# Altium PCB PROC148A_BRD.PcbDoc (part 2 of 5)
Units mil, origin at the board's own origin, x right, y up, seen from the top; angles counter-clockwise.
Board outline 7150 x 3764 mil, 4 copper layers (Top Layer, GND01, PWR/GND02, Bottom Layer), stack 60.96 mil thick; 312 components, 352 nets, 2206 pads, 423 vias.
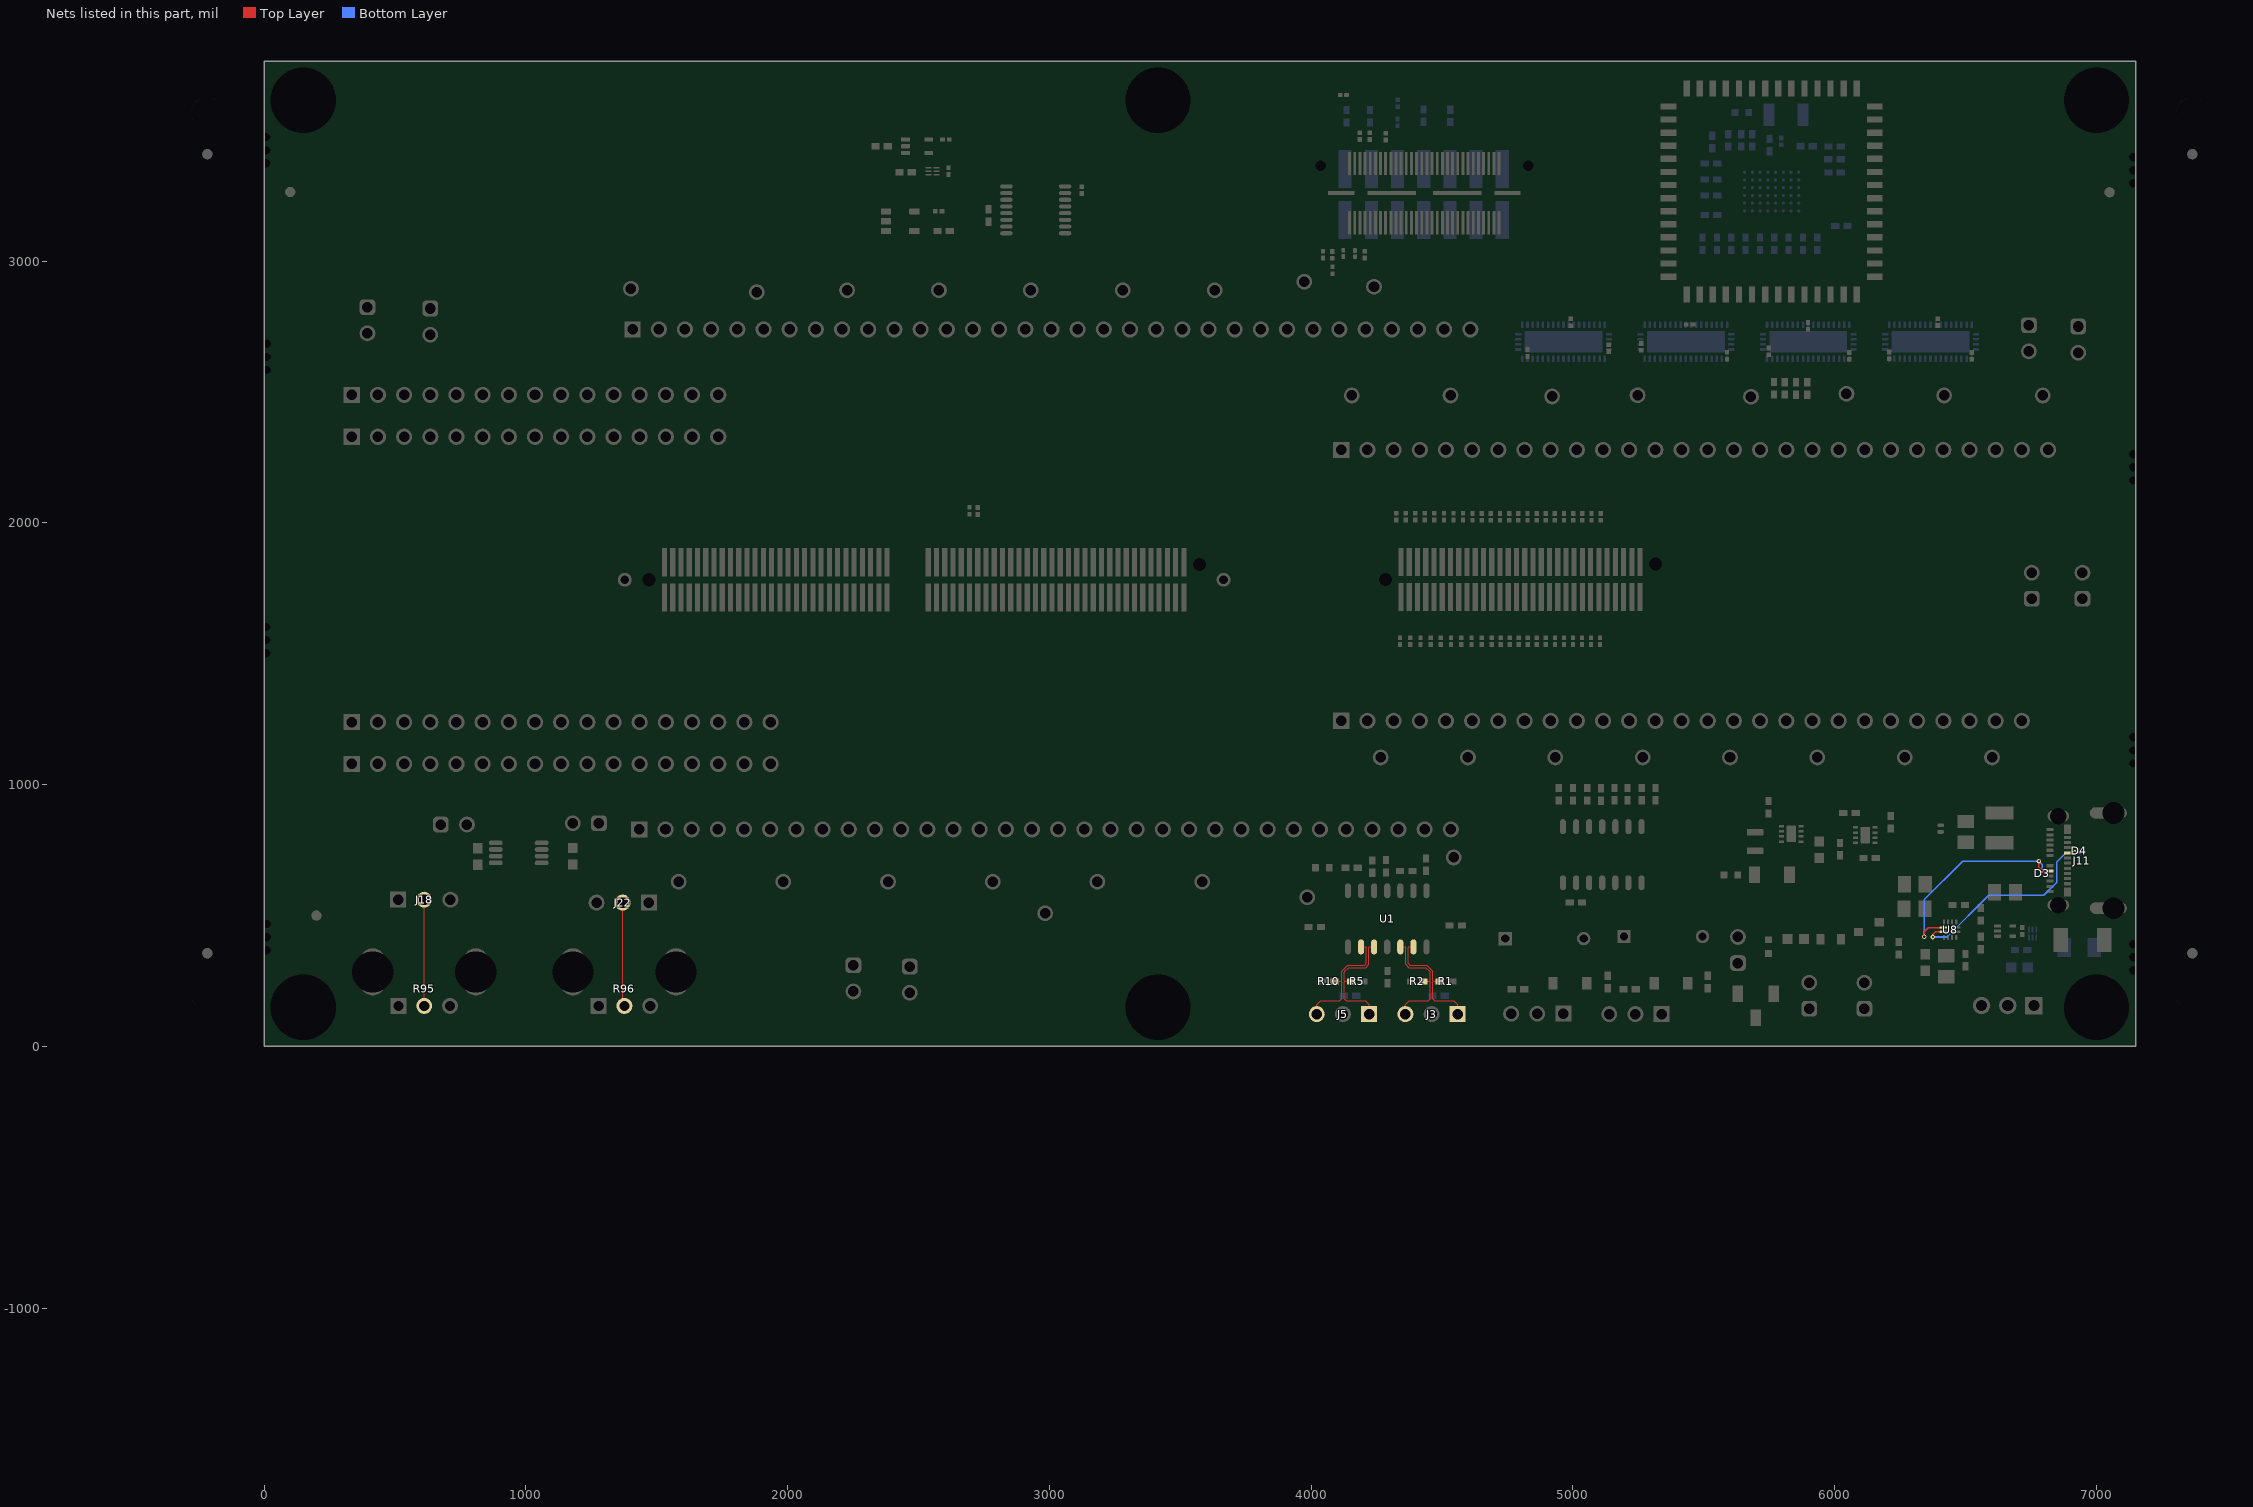
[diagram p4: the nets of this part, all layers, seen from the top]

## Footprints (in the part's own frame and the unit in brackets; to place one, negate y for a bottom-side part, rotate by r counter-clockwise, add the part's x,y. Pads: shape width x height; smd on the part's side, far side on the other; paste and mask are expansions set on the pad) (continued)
SOD-123 [mm] "On Semi recommended land pattern"
  rect 0.915x1.22 smd: 1(-1.637,0) 2(1.637,0)
  silkscreen extent -2.74,-1.17 2.03,1.17, body extent -1.93,-0.9 1.93,0.9, height 1.35
SW_CAS-120TA [mm] "COPAL ELECTRONICS"
  rect 1.6x1 smd: 1(-1.15,1.75) 2(1.15,0) 3(-1.15,-1.75)
  silkscreen extent -2,-2.85 1.4,2.92, body extent -1.4,-2.85 1.4,2.85, height 2.51
TFM201610ALMA [mm] "TDK"
  rrect17% 0.6x1.6 smd: 1(-0.9,0) 2(0.9,0)
  body extent -1.1,-0.9 1.1,0.9, height 1
TI_Stacked_Overlay_Small [mil]
  silkscreen extent -418,-98 418,98
WEEE_Minimum [mil] "WEEElie bin"
  silkscreen extent -95,-172 99,104
Wurth_60900213421 [mil] "Shunt, 2.54mm, Black"
  round 1 on Mech3: 0(0,0)
  body extent -98,-48 98,48, height 338

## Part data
C1 C2 C5: library part CMP-0006675-2, "CAP, CERM, 0.1 uF, 50 V, +/- 20%, X7R, 0402", Cap_Case=0402, Manufacturer=MuRata, Supplier Part Number 1=490-10701-1-ND, TempCo=X7R, Tolerance_%=20%, Value1=Unknown, Value2=50V, ValueDisplayed=0.1uF
C3 C4: library part CMP-0006712-2, "CAP, CERM, 4700 pF, 100 V, +/- 10%, X7R, 0402", Cap_Case=0402, Manufacturer=MuRata, Supplier Part Number 1=490-3885-1-ND, TempCo=X7R, Tolerance_%=10%, Value1=Unknown, Value2=100V, ValueDisplayed=4700pF
C6 C7: library part CMP-0084239-1, "CAP, CERM, 220 pF, 50 V,+/- 10%, X8R, AEC-Q200 Grade 0, 0402", Cap_Case=0402, Manufacturer=TDK, TempCo=X8R, Tolerance_%=10%, Value2=50V, ValueDisplayed=220pF
C8 C26 C27 C29: library part CMP-0007727-2, "CAP, CERM, 0.1 uF, 50 V, +/- 20%, X7R, 0805", Cap_Case=0805, Manufacturer=Kemet, Supplier Part Number 1=399-1169-1-ND, TempCo=X7R, Tolerance_%=20%, Value1="0.064 ohm", Value2=50V, ValueDisplayed=0.1uF
C9 C11 C12 C13 C14 C15 C16 C17 C18 C19 C20 C21 C22 C23 C24 C25 C37 C38 C39 C40 C43: library part CMP-0009717-2, "CAP, CERM, 0.1 uF, 16 V, +/- 10%, X5R, 0201", Cap_Case=0201, Manufacturer=MuRata, Supplier Part Number 1=490-9985-1-ND, TempCo=X5R, Tolerance_%=10%, Value1=Unknown, Value2=16V, ValueDisplayed=0.1uF
C10: library part CMP-0081135-1, "CAP, CERM, 10 µF, 50 V,+/- 10%, X7R, 1210", Cap_Case=1210, Manufacturer=MuRata, Supplier Part Number 1=490-10961-1-ND, TempCo=X7R, Tolerance_%=10%, Value1="0.001 ohm", Value2=50V, ValueDisplayed=10µF
C28: library part CMP-0079201-1, "CAP, CERM, 10 µF, 50 V,+/- 10%, X7R, 1210", Cap_Case=1210, Manufacturer="Samsung Electro-Mechanics", Supplier Part Number 1=1276-3388-1-ND, TempCo=X7R, Tolerance_%=10%, Value1="0.005 ohm", Value2=50V, ValueDisplayed=10µF
C30 C41: library part CMP-0007206-4, "CAP, CERM, 300 pF, 50 V, +/- 5%, C0G/NP0, 0603", Cap_Case=0603, Manufacturer=MuRata, Supplier Part Number 1=490-1438-1-ND, TempCo=C0G/NP0, Tolerance_%=5%, Value1=Unknown, Value2=50V, ValueDisplayed=300pF
C31: library part CMP-0006412-2, "CAP, CERM, 1000 pF, 50 V, +/- 5%, C0G/NP0, 0402", Cap_Case=0402, Manufacturer=MuRata, Supplier Part Number 1=490-3244-1-ND, TempCo=C0G/NP0, Tolerance_%=5%, Value1=Unknown, Value2=50V, ValueDisplayed=1000pF
C32: library part CMP-0008959-2, "CAP, CERM, 22 uF, 10 V, +/- 10%, X7R, 1206", Cap_Case=1206, Manufacturer=MuRata, Supplier Part Number 1=490-5309-1-ND, TempCo=X7R, Tolerance_%=10%, Value1=Unknown, Value2=10V, ValueDisplayed=22uF
C33: library part CMP-0007501-5, "CAP, CERM, 10 uF, 25 V, +/- 20%, X5R, 0603", Cap_Case=0603, Manufacturer=MuRata, Supplier Part Number 1=490-12323-1-ND, TempCo=X5R, Tolerance_%=20%, Value1=Unknown, Value2=25V, ValueDisplayed=10uF
C34: library part CMP-0009436-2, "CAP, CERM, 1000 pF, 2000 V, +/- 10%, X7R, 1808", Cap_Case=1808, Manufacturer=MuRata, Supplier Part Number 1=490-8145-1-ND, TempCo=X7R, Tolerance_%=10%, Value1=Unknown, Value2=2000V, ValueDisplayed=1000pF
C35 C36: library part CMP-0006608-2, "CAP, CERM, 1 uF, 25 V, +/- 10%, X5R, 0402", Cap_Case=0402, Manufacturer=MuRata, Supplier Part Number 1=490-10017-1-ND, TempCo=X5R, Tolerance_%=10%, Value1=Unknown, Value2=25V, ValueDisplayed=1uF
C44: library part CMP-0007174-4, "CAP, CERM, 0.01 uF, 50 V, +/- 5%, C0G/NP0, 0603", Cap_Case=0603, Manufacturer=MuRata, Supplier Part Number 1=490-9666-1-ND, TempCo=C0G/NP0, Tolerance_%=5%, Value1=Unknown, Value2=50V, ValueDisplayed=0.01uF
D1 D6: library part CMP-0029001-2, "Diode, Ultrafast, 100 V, 0.15 A, SOD-123", Manufacturer="Diodes Inc.", Value1=0.15A, Value2=1.25V
D2: library part CMP-0073591-4, "Automotive 1-Channel Ultra-Low-Capacitance IEC ESD Protection Diode, DPY0002A (X1SON-2)", Alternate Manufacturer="Texas Instruments", Alternate PartNumber=TPD1E05U06QDPYTQ1, Operating Temperature Range="-40 to 125 C", Rating=Automotive
D3 D4: library part CMP-0073601-1, "1-Channel ESD Protection Diode for USB Type-C and Thunderbolt 3, DPL0002A (X2SON-2)", Alternate Manufacturer="Texas Instruments", Alternate PartNumber=TPD1E01B04DPLT
D5: library part CMP-0002879-2, "LED, Green, SMD", Color=green, Manufacturer=OSRAM, Value1=W, Value2=1.8V
FB3 FB4 FB5 FB6: library part CMP-0089199-1, "120 Ohms @ 100MHz 1  Ferrite Bead 0603 (1608 Metric) 2A 40mOhm", Digikey Part Number=490-3991-1-ND, Impedance At Frequency="120O @ 100MHz", Manufacturer=Murata, Mouser Part Number=81-BLM18EG121SN1D, Operating Temperature Range="-55°C to +125°C", Tolerance_%=25%
FID1 FID2 FID3 FID4 FID5 FID6: library part CMP-0077181-1, "Fiducial mark.  There is nothing to buy or mount.", Manufacturer=N/A
J1: library part CMP-0003859-2, "C2000 controlCARD-180HSEC (60-pin addon) connector, SMT", Manufacturer=Samtec
J2: library part CMP-0003814-2, "C2000 controlCARD-120HSEC connector, SMT", Manufacturer=Samtec
J3 J5 J7 J8 J18 J22: library part CMP-0055332-1, "Header, 2.54mm, 3x1, Tin, TH", Color=Black, Current_A=4A, Manufacturer=Molex, Supplier Part Number 1=WM50016-03-ND, Voltage_V=250V
J4 J13 J16 J17 J19 J23 J26 J27 J28 J29 J30 J65 J66: library part CMP-0077643-1, "Header, 2.54mm, 2x1, Gold, TH", Color=Black, Current_A=5.7A, Manufacturer=Samtec, Supplier Part Number 1=SAM1038-02-ND, Voltage_V=550V
J6 J14: library part CMP-02766-001472-1, "CONN HEADER VERT 17POS 2.54MM", Color=Black, Package Quantity=1
J9: library part CMP-0075524-1, "Receptacle, 0.5 mm, 30x2, Gold, TH", Color=Black, Manufacturer=Samtec, PartNumber=QSH-030-01-L-D-A, Supplier Part Number 1=SAM8180-ND
J10: library part CMP-0075611-2, "Header, 2.54mm, 7x2, Gold, SMT", Color=Black, Current_A=5.4A, Manufacturer=Samtec, Supplier Part Number 1=TSM-107-01-L-DV-ND
J11: library part CMP-0093552-1, "USB-C (USB TYPE-C) USB 3.2 Gen 2 (USB 3.1 Gen 2, Superspeed + (USB 3.1)) Receptacle Connector 24 Position Surface Mount, Right Angle; Through Hole", Digikey Part Number=WM17992CT-ND, Manufacturer=Molex, Mouser Part Number=538-201267-0005, Operating Temperature Range="-40°C to +105°C", Voltage_V=30V
J12 J15: library part CMP-02766-001466-1, "CONN HEADER VERT 15POS 2.54MM", Color=Black
J20: library part CMP-02766-001470-1, "CONN HEADER VERT 32POS 2.54MM", Color=Black, Package Quantity=1
J21: library part CMP-02766-001386-1, "CONN HEADER VERT 33POS 2.54MM", Color=Black
J24: library part CMP-02766-001392-1, "CONN HEADER VERT 27POS 2.54MM", Color=Black, Package Quantity=1
J25: library part CMP-02766-001385-1, "CONN HEADER VERT 28POS 2.54MM", Color=Black, Package Quantity=1
J31 J32 J33 J34 J35 J36 J37 J38 J39 J40 J41 J42 J43 J44 J45 J46 J47 J48 J49 J50 J51 J52 J53 J54 J55 J56 J57 J58 J59 J60 J61 J62 J63 J64: library part CMP-0079328-1, "Header, 2.54mm, 1x1, Gold, TH", Color=Black, Manufacturer=Samtec, Supplier Part Number 1=SAM1038-01-ND
L1: library part CMP-0081094-1, "Inductor, Shielded, Metal Composite, 2.2 µH, 1.9 A, 0.152 ohm, AEC-Q200 Grade 0, SMD", Manufacturer=TDK, Supplier Part Number 1=445-174576-1-ND, Value1="0.152 ohm", Value2=1.9A, ValueDisplayed=2.2µH
Logo1: library part CMP-0074844-1
Logo2: library part CMP-0074838-1, "Texas Instrument Corporate Signature"
Logo3: library part CMP-0074847-1, "FCC_disclaimer"
Logo4: library part CMP-0074769-1
Q1: library part CMP-1058-00767-1, "Power MOSFET, 200 mA, 50 V, N-Channel, 3-Pin SOT-23, Pb-Free, Tape and Reel", Manufacturer="On Semiconductor", Package Type=SOT-23-3
R1 R2 R5 R10: library part CMP-0026462-2, "RES, 59.0, 1%, 0.063 W, AEC-Q200 Grade 0, 0402", Manufacturer=Vishay-Dale, Power_W=63mW, Supplier Part Number 1=541-59.0LCT-ND, TempCo="100 ppm/C", Tolerance_%=1%, Value2=0.063W, Value_Code=59R0, ValueDisplayed=59.0
R3 R6 R53 R56 R89 R92: library part CMP-0026822-3, "RES, 0, 5%, 0.063 W, AEC-Q200 Grade 0, 0402", Manufacturer=Vishay-Dale, Power_W=63mW, Supplier Part Number 1=541-0.0JCT-ND, TempCo="200 ppm/C", Tolerance_%=5%, Value2=0.063W, Value_Code=0000, ValueDisplayed=0
R4 R7 R88 R91: library part CMP-0026908-3, "RES, 33, 5%, 0.063 W, AEC-Q200 Grade 0, 0402", Manufacturer=Vishay-Dale, Power_W=63mW, Supplier Part Number 1=541-33JCT-ND, TempCo="200 ppm/C", Tolerance_%=5%, Value2=0.063W, Value_Code=33R0, ValueDisplayed=33
R8 R9: library part CMP-0026994-4, "RES, 10 k, 5%, 0.1 W, AEC-Q200 Grade 0, 0402", Manufacturer=Panasonic, Power_W=100mW, Supplier Part Number 1=P10KJCT-ND, TempCo="200 ppm/C", Tolerance_%=5%, Value2=0.1W, Value_Code=10k0, ValueDisplayed=10k
R11: library part CMP-0026829-3, "RES, 110, 5%, 0.063 W, AEC-Q200 Grade 0, 0402", Manufacturer=Vishay-Dale, Power_W=63mW, Supplier Part Number 1=541-110JCT-ND, TempCo="200 ppm/C", Tolerance_%=5%, Value2=0.063W, Value_Code=110R, ValueDisplayed=110
R12 R48 R59 R60 R61 R62 R63 R64 R65 R66 R67 R68 R69 R70 R71 R72: library part CMP-0026880-3, "RES, 22, 5%, 0.063 W, AEC-Q200 Grade 0, 0402", Manufacturer=Vishay-Dale, Power_W=63mW, Supplier Part Number 1=541-22JCT-ND, TempCo="200 ppm/C", Tolerance_%=5%, Value2=0.063W, Value_Code=22R0, ValueDisplayed=22
R13 R14 R20 R22 R37 R38 R39 R73 R74 R75 R76 R77 R78 R79 R80 R81 R82 R83 R85 R86 R87 R90 R93: library part CMP-0026825-5, "RES, 10 k, 5%, 0.063 W, AEC-Q200 Grade 0, 0402", Manufacturer=Vishay-Dale, Power_W=63mW, Supplier Part Number 1=541-10KJCT-ND, TempCo="200 ppm/C", Tolerance_%=5%, Value2=0.063W, Value_Code=10k0, ValueDisplayed=10k
R15 R16 R23: library part CMP-0083836-1, "RES, 100, 1%, 0.05 W, 0201", Manufacturer=Vishay-Semiconductor, Power_W=50mW, TempCo="100 ppm/C", Tolerance_%=1%, Value2=0.05W, Value_Code=100R, ValueDisplayed=100
R17: library part CMP-0027280-3, "RES, 4.70 k, 1%, 0.05 W, 0201", Manufacturer=Vishay-Dale, Power_W=50mW, Supplier Part Number 1=541-4.70KAABCT-ND, TempCo="100 ppm/C", Tolerance_%=1%, Value2=0.05W, Value_Code=4k70, ValueDisplayed=4.70k
R18 R19 R21: library part CMP-0089575-2, "Res Thick Film 0201 33.2 Ohm 1% 0.05W(1/20W) ±200ppm/C Pad SMD Automotive T/R", Digikey Part Number=P122945CT-ND, Manufacturer=Panasonic, Mouser Part Number=667-ERJ-1GNF33R2C, Operating Temperature Range="-55°C to +125°C", Power_W=50mW, TempCo=200ppm/°C, Tolerance_%=1%
R24 R26 R27 R28 R29 R30 R31 R32 R33 R34 R35 R40 R41 R42 R43 R44 R45 R46 R97 R98 R99 R100 R101 R102 R103 R104 R105 R106 R107 R108 R109 R110 R111 R112 R113 R114 R115 R116 R117 R118 R119 R120 R121 R122 R123 R124 R125: library part CMP-0027309-2, "RES, 10.0, 1%, 0.05 W, 0201", Manufacturer="Yageo America", Power_W=50mW, Supplier Part Number 1=311-10.0MCT-ND, TempCo="350 ppm/C", Tolerance_%=1%, Value2=0.05W, Value_Code=10R0, ValueDisplayed=10.0
R25: library part CMP-0027008-4, "RES, 0, 5%, 0.05 W, 0201", Manufacturer=Vishay-Dale, Power_W=50mW, Supplier Part Number 1=72M6743, TempCo=ppm/C, Tolerance_%=5%, Value2=0.05W, Value_Code=0000, ValueDisplayed=0
R36 R84: library part CMP-0026071-3, "RES, 1.00 k, 1%, 0.063 W, AEC-Q200 Grade 0, 0402", Manufacturer=Vishay-Dale, Power_W=63mW, Supplier Part Number 1=541-1.00KLCT-ND, TempCo="100 ppm/C", Tolerance_%=1%, Value2=0.063W, Value_Code=1k00, ValueDisplayed=1.00k
R47: library part CMP-0027015-3, "RES, 22, 5%, 0.05 W, AEC-Q200 Grade 1, 0201", Manufacturer=Panasonic, Power_W=50mW, Supplier Part Number 1=ERJ-1GNJ220C-ND, TempCo="200 ppm/C", Tolerance_%=5%, Value2=0.05W, Value_Code=22R0, ValueDisplayed=22
R49 R50: library part CMP-0026700-1, "RES, 4.70 k, 1%, 0.1 W, 0402", Manufacturer=Panasonic, Power_W=100mW, Supplier Part Number 1=P4.70KLCT-ND, TempCo="100 ppm/C", Tolerance_%=1%, Value2=0.1W, Value_Code=4k70, ValueDisplayed=4.70k
R51: library part CMP-0021811-3, "RES, 909 k, 1%, 0.125 W, AEC-Q200 Grade 0, 0805", Manufacturer=Panasonic, Power_W=125mW, Supplier Part Number 1=P909KCCT-ND, TempCo="100 ppm/C", Tolerance_%=1%, Value2=0.125W, Value_Code=909k
R52: library part CMP-0025817-4, "RES, 4.7 k, 5%, 0.1 W, AEC-Q200 Grade 0, 0603", Manufacturer=Vishay-Dale, Power_W=100mW, Supplier Part Number 1=541-4.7KGCT-ND, TempCo="200 ppm/C", Tolerance_%=5%, Value2=0.1W, Value_Code=4k70, ValueDisplayed=4.7k
R54: library part CMP-0026677-1, "RES, 200 k, 1%, 0.1 W, 0402", Manufacturer=Panasonic, Power_W=100mW, Supplier Part Number 1=P200KLCT-ND, TempCo="100 ppm/C", Tolerance_%=1%, Value2=0.1W, Value_Code=200k
R55: library part CMP-0025756-4, "RES, 220, 5%, 0.1 W, AEC-Q200 Grade 0, 0603", Manufacturer=Vishay-Dale, Power_W=100mW, Supplier Part Number 1=541-220GCT-ND, TempCo="200 ppm/C", Tolerance_%=5%, Value2=0.1W, Value_Code=220R, ValueDisplayed=220
R57: library part CMP-0016716-3, "RES, 1.00 M, 1%, 0.25 W, AEC-Q200 Grade 0, 1206", Manufacturer=Vishay-Dale, Power_W=250mW, Supplier Part Number 1=541-1.00MFCT-ND, TempCo="100 ppm/C", Tolerance_%=1%, Value2=0.25W, Value_Code=1M00, ValueDisplayed=1.00M
R58 R94: library part CMP-0025950-3, "RES, 100 k, 1%, 0.063 W, AEC-Q200 Grade 0, 0402", Manufacturer=Vishay-Dale, Power_W=63mW, Supplier Part Number 1=541-100KLCT-ND, TempCo="100 ppm/C", Tolerance_%=1%, Value2=0.063W, Value_Code=100k
R95 R96: library part CMP-0096228-1, "10k Ohm 1 Gang Linear Through Hole, Snap In Potentiometer None 1.0 Kierros Carbon 0.05W, 1/20W PC Pins, Board Locks", Digikey Part Number=PTV09A-8025U-B103-ND, Manufacturer=Bourns, Mouser Part Number=652-PTV09A-8025UB103, Operating Temperature Range="-10°C to +50°C", Power_W=0.05W, Tolerance_%=20%
S1: library part CMP-0002139-2, "Switch, Slide, SPDT  100mA, SMT", CurrentRating_mA=100A, Manufacturer="Copal Electronics", Supplier Part Number 1=CAS120JCT-ND
SH-J1 SH-J2 SH-J3 SH-J4: library part CMP-0003761-2, "Shunt, 2.54mm, Gold, Black", Manufacturer="Wurth Elektronik", Supplier Part Number 1=732-2678-ND
SW1 SW2: library part CMP-0086077-1, "Dip Switch SPST 1 Position Through Hole Slide (Standard) Actuator 25mA 24VDC", CurrentRating_mA=25mA, Manufacturer="Omron Electronics Inc-EMC Div"
SW3: library part CMP-0091791-1, "Toggle Switch SPDT Through Hole  3A 120V", Contact Current Rating=3A, Digikey Part Number=EG5771-ND, Manufacturer=E-Switch, Mouser Part Number=612-200AWMSP1T1A1M2Q, Operating Temperature Range="-30°C to +85°C"
U1: library part CMP-0074638-2, "Automotive High Speed Dual CAN Transceiver, D0014A (SOIC-14)", Alternate Manufacturer="Texas Instruments"
U2: library part CMP-0077655-1, "Automotive Dual LIN Transceiver, D0014A (SOIC-14)", Alternate Manufacturer="Texas Instruments", Alternate PartNumber=TLIN2022DTQ1
U3: library part CMP-0095867-1, "Cellular RAM Pseudo SRAM, 4Mx16, 1.7 to 1.95V, 70ns, TFBGA-48", Manufacturer=ISSI, Max Supply Voltage=3.6V, Min Supply Voltage=1.7V, Mouser Part Number=870-7WVE416EBLL70BL1, Nominal Supply Current=20-25mA, Operating Temperature Range="-40°C to +85°C"
U4 U5 U6 U7: library part CMP-0093539-2, "IC MUX/DEMUX DDR3 1:2 42WQFN", Digikey Part Number=296-28307-1-ND, Manufacturer="Texas Instruments", Max Supply Voltage=3.6V, Min Supply Voltage=3V, Mouser Part Number=595-TS3DDR3812RUAR, Nominal Supply Current=300uA, On State Resistance=8O, Operating Temperature Range="-40°C to +85°C"
U8: library part CMP-0073634-2, "USB Type-C  for USB 2.0 CC Port Controller, RWB0012A (X2QFN-12)", Alternate Manufacturer="Texas Instruments", Operating Temperature Range="-40 to 85 C", Rating=Catalog
U9: library part CMP-0051530-2, "Single 2-Input Positive-NOR Gate, DRL0005A, LARGE T&R", Alternate Manufacturer="Texas Instruments", F @ Nom Voltage(Max)(Mhz)=75, Generic Part Number=SN74AHC1G02, ICC @ Nom Voltage(Max)(mA)=0.01, Operating Temperature Range(C)="-40 to 125,-40 to 85", Rating=Catalog, tpd @ Nom Voltage(Max)(ns)=11.4,7.5, Voltage(Nom)(V)=3.3,5
U10: library part CMP-04913-000004-1, "IC PWR SWITCH N-CHAN 1:1 8WSON", Ambient Temperature Range High=+105°C, Ambient Temperature Range Low=-40°C, Manufacturer="Texas Instruments", Max Junction Temp=+125°C, Max Supply Voltage=5.7V, Min Supply Voltage=2.5V, Nominal Supply Current=20-50uA, On State Resistance=16mO, Output Current=6A, Output Voltage=0.8-5.7V, Package=DSG0008A, TEMPERATURE="-40°C to +105°C"
U11: library part CMP-0037798-2, "Buck Step Down Regulator with 3 to 17 V Input and 3.3 V Output, -40 to 85 degC, 8-Pin WSON (DSG), Green (RoHS & no Sb/Br)", Manufacturer="Texas Instruments", Rating=Catalog, Switch Current Limit(Typ)(A)=1.05
U12: library part CMP-0076540-1, "4-Bit One-of-2 FET Multiplexer/Demultiplexer 2.5-V/3.3-V Low-Voltage, High-Bandwidth Bus Switch, PW0016A (TSSOP-16)", Alternate Manufacturer="Texas Instruments"
U13: library part CMP-0051684-3, "Single Inverter, DCK0005A, LARGE T&R", F @ Nom Voltage(Max)(Mhz)=150, Generic Part Number=SN74LVC1G04, ICC @ Nom Voltage(Max)(mA)=0.01, Manufacturer="Texas Instruments", Operating Temperature Range(C)="-40 to 125,-40 to 85", Rating=Catalog, tpd @ Nom Voltage(Max)(ns)=7.5,5.2,4.2,3.7, Voltage(Nom)(V)=1.8,2.5,3.3,5
U14 U18: library part CMP-0051419-5, "Single 2-Input Positive-AND Gate, DSF0006A, LARGE T&R", Alternate Manufacturer="Texas Instruments", F @ Nom Voltage(Max)(Mhz)=150, Generic Part Number=SN74LVC1G08, ICC @ Nom Voltage(Max)(mA)=0.01, Operating Temperature Range(C)="-40 to 125,-40 to 85", Rating=Catalog, tpd @ Nom Voltage(Max)(ns)=4.5,6,4,5, Voltage(Nom)(V)=1.8,2.5,3.3,5
U15: library part CMP-0051529-2, "Single 2-Input Positive-NOR Gate, DBV0005A (SOT-23-5)", F @ Nom Voltage(Max)(Mhz)=75, Generic Part Number=SN74AHC1G02, ICC @ Nom Voltage(Max)(mA)=0.01, Manufacturer="Texas Instruments", Operating Temperature Range="-40 to 125 C", Rating=Catalog, tpd @ Nom Voltage(Max)(ns)=11.4,7.5, Voltage(Nom)(V)=3.3,5
U16: library part CMP-0013309-4, "OPA2837DGK, DGK0008A (VSSOP-8)", Alternate Manufacturer="Texas Instruments"
ZZ1: library part CMP-0003616-3
ZZ2: library part CMP-0077236-1
ZZ3: library part CMP-0077237-1
ZZ4: library part CMP-0077238-1

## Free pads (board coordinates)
  round 0.01 on Mech5: 1(-691.22,-1531.82) 1(-691.2,-1531.33) 1(-690.94,-1530.69) 1(-690.11,-1530.74) 1(-690.04,-1530.89) 1(-689.31,-1531.4) 1(-689.31,-1530.74) 1(-689.28,-1530.88) 1(-689.02,-1531.25) 1(-688.5,-1529.82) 1(-686.8,-1531.48) 1(-686.39,-1531.17)
  round 0.04 on Mech5: 1(-690.56,-1530.37) 1(-690.56,-1530.27) 1(-690.56,-1530.17) 1(-690.56,-1530.07) 1(-690.56,-1529.97) 1(-690.56,-1529.87) 1(-690.56,-1529.77) 1(-690.46,-1530.37) 1(-690.46,-1530.27) 1(-690.46,-1530.17) 1(-690.46,-1530.07) 1(-690.46,-1529.97) 1(-690.46,-1529.87) 1(-690.46,-1529.77) 1(-690.36,-1530.37) 1(-690.36,-1530.27) 1(-690.36,-1530.17) 1(-690.36,-1530.07) 1(-690.36,-1529.97) 1(-690.36,-1529.87) 1(-690.36,-1529.77) 1(-690.26,-1530.37) 1(-690.26,-1530.27) 1(-690.26,-1530.17) 1(-690.26,-1530.07) 1(-690.26,-1529.97) 1(-690.26,-1529.87) 1(-690.26,-1529.77) 1(-690.16,-1532.37) 1(-690.16,-1532.27) 1(-690.16,-1532.17) 1(-690.16,-1532.07) 1(-690.16,-1531.97) 1(-690.16,-1531.87) 1(-690.16,-1531.77) 1(-690.16,-1530.37) 1(-690.16,-1530.27) 1(-690.16,-1530.17) 1(-690.16,-1530.07) 1(-690.16,-1529.97) 1(-690.16,-1529.87) 1(-690.16,-1529.77) 1(-690.06,-1532.37) 1(-690.06,-1532.27) 1(-690.06,-1532.17) 1(-690.06,-1532.07) 1(-690.06,-1531.97) 1(-690.06,-1531.87) 1(-690.06,-1531.77) 1(-690.06,-1530.37) 1(-690.06,-1530.27) 1(-690.06,-1530.17) 1(-690.06,-1530.07) 1(-690.06,-1529.97) 1(-690.06,-1529.87) 1(-690.06,-1529.77) 1(-689.96,-1532.37) 1(-689.96,-1532.27) 1(-689.96,-1532.17) 1(-689.96,-1532.07) 1(-689.96,-1531.97) 1(-689.96,-1531.87) 1(-689.96,-1531.77) 1(-689.96,-1530.37) 1(-689.96,-1530.27) 1(-689.96,-1530.17) 1(-689.96,-1530.07) 1(-689.96,-1529.97) 1(-689.96,-1529.87) 1(-689.96,-1529.77) 1(-689.86,-1532.37) 1(-689.86,-1532.27) 1(-689.86,-1532.17) 1(-689.86,-1532.07) 1(-689.86,-1531.97) 1(-689.86,-1531.87) 1(-689.86,-1531.77) 1(-689.86,-1530.37) 1(-689.86,-1530.27) 1(-689.86,-1530.17) 1(-689.86,-1530.07) 1(-689.86,-1529.97) 1(-689.86,-1529.87) 1(-689.86,-1529.77) 1(-689.76,-1532.37) 1(-689.76,-1532.27) 1(-689.76,-1532.17) 1(-689.76,-1532.07) 1(-689.76,-1531.97) 1(-689.76,-1531.87) 1(-689.76,-1531.77) 1(-689.76,-1530.37) 1(-689.76,-1530.27) 1(-689.76,-1530.17) 1(-689.76,-1530.07) 1(-689.76,-1529.97) 1(-689.76,-1529.87) 1(-689.76,-1529.77) 1(-689.66,-1532.37) 1(-689.66,-1532.27) 1(-689.66,-1532.17) 1(-689.66,-1532.07) 1(-689.66,-1531.97) 1(-689.66,-1531.87) 1(-689.66,-1531.77) 1(-689.66,-1530.37) 1(-689.66,-1530.27) 1(-689.66,-1530.17) 1(-689.66,-1530.07) 1(-689.66,-1529.97) 1(-689.66,-1529.87) 1(-689.66,-1529.77) 1(-689.56,-1532.37) 1(-689.56,-1532.27) 1(-689.56,-1532.17) 1(-689.56,-1532.07) 1(-689.56,-1531.97) 1(-689.56,-1531.87) 1(-689.56,-1531.77) 1(-689.56,-1530.37) 1(-689.56,-1530.27) 1(-689.56,-1530.17) 1(-689.56,-1530.07) 1(-689.56,-1529.97) 1(-689.56,-1529.87) 1(-689.56,-1529.77) 1(-689.46,-1532.37) 1(-689.46,-1532.27) 1(-689.46,-1532.17) 1(-689.46,-1532.07) 1(-689.46,-1531.97) 1(-689.46,-1531.87) 1(-689.46,-1531.77) 1(-689.46,-1530.37) 1(-689.46,-1530.27) 1(-689.46,-1530.17) 1(-689.46,-1530.07) 1(-689.46,-1529.97) 1(-689.46,-1529.87) 1(-689.46,-1529.77) 1(-689.36,-1532.37) 1(-689.36,-1532.27) 1(-689.36,-1532.17) 1(-689.36,-1532.07) 1(-689.36,-1531.97) 1(-689.36,-1531.87) 1(-689.36,-1531.77) 1(-689.36,-1530.37) 1(-689.36,-1530.27) 1(-689.36,-1530.17) 1(-689.36,-1530.07) 1(-689.36,-1529.97) 1(-689.36,-1529.87) 1(-689.36,-1529.77) 1(-689.26,-1532.37) 1(-689.26,-1532.27) 1(-689.26,-1532.17) 1(-689.26,-1532.07) 1(-689.26,-1531.97) 1(-689.26,-1531.87) 1(-689.26,-1531.77) 1(-689.26,-1530.37) 1(-689.26,-1530.27) 1(-689.26,-1530.17) 1(-689.26,-1530.07) 1(-689.26,-1529.97) 1(-689.26,-1529.87) 1(-689.26,-1529.77) 1(-689.16,-1532.37) 1(-689.16,-1532.27) 1(-689.16,-1532.17) 1(-689.16,-1532.07) 1(-689.16,-1531.97) 1(-689.16,-1531.87) 1(-689.16,-1531.77) 1(-689.16,-1530.37) 1(-689.16,-1530.27) 1(-689.16,-1530.17) 1(-689.16,-1530.07) 1(-689.16,-1529.97) 1(-689.16,-1529.87) 1(-689.16,-1529.77) 1(-689.06,-1532.37) 1(-689.06,-1532.27) 1(-689.06,-1532.17) 1(-689.06,-1532.07) 1(-689.06,-1531.97) 1(-689.06,-1531.87) 1(-689.06,-1531.77) 1(-689.06,-1530.37) 1(-689.06,-1530.27) 1(-689.06,-1530.17) 1(-689.06,-1530.07) 1(-689.06,-1529.97) 1(-689.06,-1529.87) 1(-689.06,-1529.77) 1(-688.96,-1532.37) 1(-688.96,-1532.27) 1(-688.96,-1532.17) 1(-688.96,-1532.07) 1(-688.96,-1531.97) 1(-688.96,-1531.87) 1(-688.96,-1531.77) 1(-688.96,-1530.37) 1(-688.96,-1530.27) 1(-688.96,-1530.17) 1(-688.96,-1530.07) 1(-688.96,-1529.97) 1(-688.96,-1529.87) 1(-688.96,-1529.77) 1(-688.86,-1532.37) 1(-688.86,-1532.27) 1(-688.86,-1532.17) 1(-688.86,-1532.07) 1(-688.86,-1531.97) 1(-688.86,-1531.87) 1(-688.86,-1531.77) 1(-688.86,-1530.37) 1(-688.86,-1530.27) 1(-688.86,-1530.17) 1(-688.86,-1530.07) 1(-688.86,-1529.97) 1(-688.86,-1529.87) 1(-688.86,-1529.77) 1(-688.76,-1532.37) 1(-688.76,-1532.27) 1(-688.76,-1532.17) 1(-688.76,-1532.07) 1(-688.76,-1531.97) 1(-688.76,-1531.87) 1(-688.76,-1531.77) 1(-688.76,-1530.37) 1(-688.76,-1530.27) 1(-688.76,-1530.17) 1(-688.76,-1530.07) 1(-688.76,-1529.97) 1(-688.76,-1529.87) 1(-688.76,-1529.77) 1(-688.66,-1532.37) 1(-688.66,-1532.27) 1(-688.66,-1532.17) 1(-688.66,-1532.07) 1(-688.66,-1531.97) 1(-688.66,-1531.87) 1(-688.66,-1531.77) 1(-688.66,-1530.37) 1(-688.66,-1530.27) 1(-688.66,-1530.17) 1(-688.66,-1530.07) 1(-688.66,-1529.97) 1(-688.66,-1529.87) 1(-688.66,-1529.77) 1(-688.56,-1532.37) 1(-688.56,-1532.27) 1(-688.56,-1532.17) 1(-688.56,-1532.07) 1(-688.56,-1531.97) 1(-688.56,-1531.87) 1(-688.56,-1531.77) 1(-688.56,-1530.37) 1(-688.56,-1530.27) 1(-688.56,-1530.17) 1(-688.56,-1530.07) 1(-688.56,-1529.97) 1(-688.56,-1529.87) 1(-688.56,-1529.77) 1(-688.46,-1532.37) 1(-688.46,-1532.27) 1(-688.46,-1532.17) 1(-688.46,-1532.07) 1(-688.46,-1531.97) 1(-688.46,-1531.87) 1(-688.46,-1531.77) 1(-688.46,-1530.37) 1(-688.46,-1530.27) 1(-688.46,-1530.17) 1(-688.46,-1530.07) 1(-688.46,-1529.97) 1(-688.46,-1529.87) 1(-688.46,-1529.77) 1(-688.36,-1532.37) 1(-688.36,-1532.27) 1(-688.36,-1532.17) 1(-688.36,-1532.07) 1(-688.36,-1531.97) 1(-688.36,-1531.87) 1(-688.36,-1531.77) 1(-688.36,-1530.37) 1(-688.36,-1530.27) 1(-688.36,-1530.17) 1(-688.36,-1530.07) 1(-688.36,-1529.97) 1(-688.26,-1532.37) 1(-688.26,-1532.27) 1(-688.26,-1532.17) 1(-688.26,-1532.07) 1(-688.26,-1531.97) 1(-688.26,-1531.87) 1(-688.26,-1531.77) 1(-688.26,-1530.37) 1(-688.26,-1530.27) 1(-688.26,-1530.17) 1(-688.26,-1530.07) 1(-688.26,-1529.97) 1(-688.16,-1532.37) 1(-688.16,-1532.27) 1(-688.16,-1532.17) 1(-688.16,-1532.07) 1(-688.16,-1531.97) 1(-688.16,-1531.87) 1(-688.16,-1531.77) 1(-688.16,-1530.37) 1(-688.16,-1530.27) 1(-688.16,-1530.17) 1(-688.16,-1530.07) 1(-688.16,-1529.97) 1(-688.06,-1532.37) 1(-688.06,-1532.27) 1(-688.06,-1532.17) 1(-688.06,-1532.07) 1(-688.06,-1531.97) 1(-688.06,-1531.87) 1(-688.06,-1531.77) 1(-688.06,-1530.37) 1(-688.06,-1530.27) 1(-688.06,-1530.17) 1(-688.06,-1530.07) 1(-688.06,-1529.97) 1(-687.96,-1532.37) 1(-687.96,-1532.27) 1(-687.96,-1532.17) 1(-687.96,-1532.07) 1(-687.96,-1531.97) 1(-687.96,-1531.87) 1(-687.96,-1531.77) 1(-687.96,-1530.37) 1(-687.96,-1530.27) 1(-687.96,-1530.17) 1(-687.96,-1530.07) 1(-687.96,-1529.97) 1(-687.86,-1532.37) 1(-687.86,-1532.27) 1(-687.86,-1532.17) 1(-687.86,-1532.07) 1(-687.86,-1531.97) 1(-687.86,-1531.87) 1(-687.86,-1531.77) 1(-687.86,-1530.37) 1(-687.86,-1530.27) 1(-687.86,-1530.17) 1(-687.86,-1530.07) 1(-687.86,-1529.97) 1(-687.86,-1529.87) 1(-687.86,-1529.77) 1(-687.76,-1532.37) 1(-687.76,-1532.27) 1(-687.76,-1532.17) 1(-687.76,-1532.07) 1(-687.76,-1531.97) 1(-687.76,-1531.87) 1(-687.76,-1531.77) 1(-687.76,-1530.37) 1(-687.76,-1530.27) 1(-687.76,-1530.17) 1(-687.76,-1530.07) 1(-687.76,-1529.97) 1(-687.76,-1529.87) 1(-687.76,-1529.77) 1(-687.66,-1532.37) 1(-687.66,-1532.27) 1(-687.66,-1532.17) 1(-687.66,-1532.07) 1(-687.66,-1531.97) 1(-687.66,-1531.87) 1(-687.66,-1531.77) 1(-687.66,-1530.37) 1(-687.66,-1530.27) 1(-687.66,-1530.17) 1(-687.66,-1530.07) 1(-687.66,-1529.97) 1(-687.66,-1529.87) 1(-687.66,-1529.77) 1(-687.56,-1532.37) 1(-687.56,-1532.27) 1(-687.56,-1532.17) 1(-687.56,-1532.07) 1(-687.56,-1531.97) 1(-687.56,-1531.87) 1(-687.56,-1531.77) 1(-687.56,-1530.37) 1(-687.56,-1530.27) 1(-687.56,-1530.17) 1(-687.56,-1530.07) 1(-687.56,-1529.97) 1(-687.56,-1529.87) 1(-687.56,-1529.77) 1(-687.46,-1532.37) 1(-687.46,-1532.27) 1(-687.46,-1532.17) 1(-687.46,-1532.07) 1(-687.46,-1531.97) 1(-687.46,-1531.87) 1(-687.46,-1531.77) 1(-687.46,-1530.37) 1(-687.46,-1530.27) 1(-687.46,-1530.17) 1(-687.46,-1530.07) 1(-687.46,-1529.97) 1(-687.46,-1529.87) 1(-687.46,-1529.77) 1(-687.36,-1532.37) 1(-687.36,-1532.27) 1(-687.36,-1532.17) 1(-687.36,-1532.07) 1(-687.36,-1531.97) 1(-687.36,-1531.87) 1(-687.36,-1531.77) 1(-687.36,-1530.37) 1(-687.36,-1530.27) 1(-687.36,-1530.17) 1(-687.36,-1530.07) 1(-687.36,-1529.97) 1(-687.36,-1529.87) 1(-687.36,-1529.77) 1(-687.16,-1532.37) 1(-687.16,-1532.27) 1(-687.16,-1532.17) 1(-687.16,-1532.07) 1(-687.16,-1531.97) 1(-687.16,-1531.87) 1(-687.16,-1531.77) 1(-687.16,-1530.37) 1(-687.16,-1530.27) 1(-687.16,-1530.17) 1(-687.16,-1530.07) 1(-687.16,-1529.97) 1(-687.16,-1529.87) 1(-687.16,-1529.77) 1(-687.06,-1532.37) 1(-687.06,-1532.27) 1(-687.06,-1532.17) 1(-687.06,-1532.07) 1(-687.06,-1531.97) 1(-687.06,-1531.87) 1(-687.06,-1531.77) 1(-687.06,-1530.37) 1(-687.06,-1530.27) 1(-687.06,-1530.17) 1(-687.06,-1530.07) 1(-687.06,-1529.97) 1(-687.06,-1529.87) 1(-687.06,-1529.77) 1(-686.96,-1532.37) 1(-686.96,-1532.27) 1(-686.96,-1532.17) 1(-686.96,-1532.07) 1(-686.96,-1531.97) 1(-686.96,-1531.87) 1(-686.96,-1531.77) 1(-686.96,-1530.37) 1(-686.96,-1530.27) 1(-686.96,-1530.17) 1(-686.96,-1530.07) 1(-686.96,-1529.97) 1(-686.96,-1529.87) 1(-686.96,-1529.77) 1(-686.86,-1532.37) 1(-686.86,-1532.27) 1(-686.86,-1532.17) 1(-686.86,-1532.07) 1(-686.86,-1531.97) 1(-686.86,-1531.87) 1(-686.86,-1531.77) 1(-686.86,-1530.37) 1(-686.86,-1530.27) 1(-686.86,-1530.17) 1(-686.86,-1530.07) 1(-686.86,-1529.97) 1(-686.86,-1529.87) 1(-686.86,-1529.77) 1(-686.76,-1532.37) 1(-686.76,-1532.27) 1(-686.76,-1532.17) 1(-686.76,-1532.07) 1(-686.76,-1531.97) 1(-686.76,-1531.87) 1(-686.76,-1531.77) 1(-686.76,-1530.37) 1(-686.76,-1530.27) 1(-686.76,-1530.17) 1(-686.76,-1530.07) 1(-686.76,-1529.97) 1(-686.76,-1529.87) 1(-686.76,-1529.77) 1(-686.66,-1532.37) 1(-686.66,-1532.27) 1(-686.66,-1532.17) 1(-686.66,-1532.07) 1(-686.66,-1531.97) 1(-686.66,-1531.87) 1(-686.66,-1531.77) 1(-686.66,-1530.37) 1(-686.66,-1530.27) 1(-686.66,-1530.17) 1(-686.66,-1530.07) 1(-686.66,-1529.97) 1(-686.66,-1529.87) 1(-686.66,-1529.77) 1(-686.56,-1532.37) 1(-686.56,-1532.27) 1(-686.56,-1532.17) 1(-686.56,-1532.07) 1(-686.56,-1531.97) 1(-686.56,-1531.87) 1(-686.56,-1531.77) 1(-686.56,-1530.37) 1(-686.56,-1530.27) 1(-686.56,-1530.17) 1(-686.56,-1530.07) 1(-686.56,-1529.97) 1(-686.56,-1529.87) 1(-686.56,-1529.77) 1(-686.46,-1532.37) 1(-686.46,-1532.27) 1(-686.46,-1532.17) 1(-686.46,-1532.07) 1(-686.46,-1531.97) 1(-686.46,-1531.87) 1(-686.46,-1531.77) 1(-686.46,-1530.37) 1(-686.46,-1530.27) 1(-686.46,-1530.17) 1(-686.46,-1530.07) 1(-686.46,-1529.97) 1(-686.46,-1529.87) 1(-686.46,-1529.77) 1(-686.36,-1532.37) 1(-686.36,-1532.27) 1(-686.36,-1532.17) 1(-686.36,-1532.07) 1(-686.36,-1531.97) 1(-686.36,-1531.87) 1(-686.36,-1531.77) 1(-686.36,-1530.37) 1(-686.36,-1530.27) 1(-686.36,-1530.17) 1(-686.36,-1530.07) 1(-686.36,-1529.97) 1(-686.36,-1529.87) 1(-686.36,-1529.77) 1(-686.26,-1532.37) 1(-686.26,-1532.27) 1(-686.26,-1532.17) 1(-686.26,-1532.07) 1(-686.26,-1531.97) 1(-686.26,-1531.87) 1(-686.26,-1531.77) 1(-686.26,-1530.37) 1(-686.26,-1530.27) 1(-686.26,-1530.17) 1(-686.26,-1530.07) 1(-686.26,-1529.97) 1(-686.26,-1529.87) 1(-686.26,-1529.77) 1(-686.16,-1532.37) 1(-686.16,-1532.27) 1(-686.16,-1532.17) 1(-686.16,-1532.07) 1(-686.16,-1531.97) 1(-686.16,-1531.87) 1(-686.16,-1531.77) 1(-686.16,-1530.37) 1(-686.16,-1530.27) 1(-686.16,-1530.17) 1(-686.16,-1530.07) 1(-686.16,-1529.97) 1(-686.16,-1529.87) 1(-686.16,-1529.77) 1(-686.06,-1532.37) 1(-686.06,-1532.27) 1(-686.06,-1532.17) 1(-686.06,-1532.07) 1(-686.06,-1531.97) 1(-686.06,-1531.87) 1(-686.06,-1531.77) 1(-686.06,-1530.37) 1(-686.06,-1530.27) 1(-686.06,-1530.17) 1(-686.06,-1530.07) 1(-686.06,-1529.97) 1(-686.06,-1529.87) 1(-686.06,-1529.77) 1(-685.96,-1532.37) 1(-685.96,-1532.27) 1(-685.96,-1532.17) 1(-685.96,-1532.07) 1(-685.96,-1531.97) 1(-685.96,-1531.87) 1(-685.96,-1531.77) 1(-685.96,-1530.37) 1(-685.96,-1530.27) 1(-685.96,-1530.17) 1(-685.96,-1530.07) 1(-685.96,-1529.97) 1(-685.96,-1529.87) 1(-685.96,-1529.77) 1(-685.86,-1532.37) 1(-685.86,-1532.27) 1(-685.86,-1532.17) 1(-685.86,-1532.07) 1(-685.86,-1531.97) 1(-685.86,-1531.87) 1(-685.86,-1531.77) 1(-685.86,-1530.37) 1(-685.86,-1530.27) 1(-685.86,-1530.17) 1(-685.86,-1530.07) 1(-685.86,-1529.97) 1(-685.86,-1529.87) 1(-685.86,-1529.77) 1(-685.76,-1532.37) 1(-685.76,-1532.27) 1(-685.76,-1532.17) 1(-685.76,-1532.07) 1(-685.76,-1531.97) 1(-685.76,-1531.87) 1(-685.76,-1531.77) 1(-685.76,-1530.37) 1(-685.76,-1530.27) 1(-685.76,-1530.17) 1(-685.76,-1530.07) 1(-685.76,-1529.97) 1(-685.76,-1529.87) 1(-685.76,-1529.77) 1(-685.66,-1532.37) 1(-685.66,-1532.27) 1(-685.66,-1532.17) 1(-685.66,-1532.07) 1(-685.66,-1531.97) 1(-685.66,-1531.87) 1(-685.66,-1531.77) 1(-685.66,-1530.37) 1(-685.66,-1530.27) 1(-685.66,-1530.17) 1(-685.66,-1530.07) 1(-685.66,-1529.97) 1(-685.66,-1529.87) 1(-685.66,-1529.77) 1(-685.56,-1532.37) 1(-685.56,-1532.27) 1(-685.56,-1532.17) 1(-685.56,-1532.07) 1(-685.56,-1531.97) 1(-685.56,-1531.87) 1(-685.56,-1531.77) 1(-685.56,-1530.37) 1(-685.56,-1530.27) 1(-685.56,-1530.17) 1(-685.56,-1530.07) 1(-685.56,-1529.97) 1(-685.56,-1529.87) 1(-685.56,-1529.77) 1(-685.46,-1532.37) 1(-685.46,-1532.27) 1(-685.46,-1532.17) 1(-685.46,-1532.07) 1(-685.46,-1531.97) 1(-685.46,-1531.87) 1(-685.46,-1531.77) 1(-685.46,-1530.37) 1(-685.46,-1530.27) 1(-685.46,-1530.17) 1(-685.46,-1530.07) 1(-685.46,-1529.97) 1(-685.46,-1529.87) 1(-685.46,-1529.77) 1(-685.36,-1532.37) 1(-685.36,-1532.27) 1(-685.36,-1532.17) 1(-685.36,-1532.07) 1(-685.36,-1531.97) 1(-685.36,-1531.87) 1(-685.36,-1531.77) 1(-685.36,-1530.37) 1(-685.36,-1530.27) 1(-685.36,-1530.17) 1(-685.36,-1530.07) 1(-685.36,-1529.97) 1(-685.36,-1529.87) 1(-685.36,-1529.77) 1(-685.26,-1532.37) 1(-685.26,-1532.27) 1(-685.26,-1532.17) 1(-685.26,-1532.07) 1(-685.26,-1531.97) 1(-685.26,-1531.87) 1(-685.26,-1531.77) 1(-685.26,-1530.37) 1(-685.26,-1530.27) 1(-685.26,-1530.17) 1(-685.26,-1530.07) 1(-685.26,-1529.97) 1(-685.26,-1529.87) 1(-685.26,-1529.77) 1(-685.16,-1532.37) 1(-685.16,-1532.27) 1(-685.16,-1532.17) 1(-685.16,-1532.07) 1(-685.16,-1531.97) 1(-685.16,-1531.87) 1(-685.16,-1531.77) 1(-685.16,-1530.37) 1(-685.16,-1530.27) 1(-685.16,-1530.17) 1(-685.16,-1530.07) 1(-685.16,-1529.97) 1(-685.16,-1529.87) 1(-685.16,-1529.77) 1(-685.06,-1532.37) 1(-685.06,-1532.27) 1(-685.06,-1532.17) 1(-685.06,-1532.07) 1(-685.06,-1531.97) 1(-685.06,-1531.87) 1(-685.06,-1531.77) 1(-685.06,-1530.37) 1(-685.06,-1530.27) 1(-685.06,-1530.17) 1(-685.06,-1530.07) 1(-685.06,-1529.97) 1(-685.06,-1529.87) 1(-685.06,-1529.77) 1(-684.96,-1532.37) 1(-684.96,-1532.27) 1(-684.96,-1532.17) 1(-684.96,-1532.07) 1(-684.96,-1531.97) 1(-684.96,-1531.87) 1(-684.96,-1531.77) 1(-684.96,-1530.37) 1(-684.96,-1530.27) 1(-684.96,-1530.17) 1(-684.96,-1530.07) 1(-684.96,-1529.97) 1(-684.96,-1529.87) 1(-684.96,-1529.77) 1(-684.86,-1532.37) 1(-684.86,-1532.27) 1(-684.86,-1532.17) 1(-684.86,-1532.07) 1(-684.86,-1531.97) 1(-684.86,-1531.87) 1(-684.86,-1531.77) 1(-684.86,-1530.37) 1(-684.86,-1530.27) 1(-684.86,-1530.17) 1(-684.86,-1530.07) 1(-684.86,-1529.97) 1(-684.86,-1529.87) 1(-684.86,-1529.77) 1(-684.76,-1532.37) 1(-684.76,-1532.27) 1(-684.76,-1532.17) 1(-684.76,-1532.07) 1(-684.76,-1531.97) 1(-684.76,-1531.87) 1(-684.76,-1531.77) 1(-684.76,-1530.37) 1(-684.76,-1530.27) 1(-684.76,-1530.17) 1(-684.76,-1530.07) 1(-684.76,-1529.97) 1(-684.76,-1529.87) 1(-684.76,-1529.77) 1(-684.66,-1532.37) 1(-684.66,-1532.27) 1(-684.66,-1532.17) 1(-684.66,-1532.07) 1(-684.66,-1531.97) 1(-684.66,-1531.87) 1(-684.66,-1531.77) 1(-684.66,-1530.37) 1(-684.66,-1530.27) 1(-684.66,-1530.17) 1(-684.66,-1530.07) 1(-684.66,-1529.97) 1(-684.66,-1529.87) 1(-684.66,-1529.77) 1(-684.56,-1532.37) 1(-684.56,-1532.27) 1(-684.56,-1532.17) 1(-684.56,-1532.07) 1(-684.56,-1531.97) 1(-684.56,-1531.87) 1(-684.56,-1531.77) 1(-684.56,-1530.37) 1(-684.56,-1530.27) 1(-684.56,-1530.17) 1(-684.56,-1530.07) 1(-684.56,-1529.97) 1(-684.56,-1529.87) 1(-684.56,-1529.77) 1(-684.46,-1532.37) 1(-684.46,-1532.27) 1(-684.46,-1532.17) 1(-684.46,-1532.07) 1(-684.46,-1531.97) 1(-684.46,-1531.87) 1(-684.46,-1531.77) 1(-684.46,-1530.37) 1(-684.46,-1530.27) 1(-684.46,-1530.17) 1(-684.46,-1530.07) 1(-684.46,-1529.97) 1(-684.46,-1529.87) 1(-684.46,-1529.77)

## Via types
v1: diameter 18, hole 8, Top Layer to Bottom Layer, tented both sides, 422 vias
v2: diameter 18, hole 8, Top Layer to Bottom Layer, 1 vias

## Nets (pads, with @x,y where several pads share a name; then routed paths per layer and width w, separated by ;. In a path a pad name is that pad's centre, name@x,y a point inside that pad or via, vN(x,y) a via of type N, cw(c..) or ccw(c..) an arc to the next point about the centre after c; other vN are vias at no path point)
ADC_POT1_OUT: J18.2 R95.2 | length 405.7
  Top Layer w4: R95.2@611.85,154.79 J18.2@611.85,560.53
ADC_POT2_OUT: J22.2 R96.2 | length 397.2
  Top Layer w4: J22.2@1370,549.3 1370,161.37 R96.2@1376.57,154.79
C_A5_CC1: D3.2 J11.A5 U8.1 | length 854.5
  Top Layer w6: v1(6341.97,419) 6341.97,437.97 6357.81,453.81 U8.1@6415,453.81 ; v1(6780,707.76) 6780,685 6793.15,671.85 6820.71,671.85 J11.A5@6821.93,670.63
  Bottom Layer w6: v1(6341.97,419) 6341.97,554.61 6341.34,555.24 6341.34,560.22 6488.88,707.76 v1(6780,707.76) 6792.77,694.99 D3.2@6792.77,668.95
C_B5_CC2: D4.2 J11.B5 U8.2 | length 822.6
  Top Layer w6: v1(6375,418) 6374.99,427.99 6385.06,438.06 U8.2@6415,438.06 ; J11.B5@6888.86,739.53 6890.02,740.69 v1(6916.98,740.69)
  Bottom Layer w6: v1(6375,418) 6428.93,418 6588.02,577.09 6798.8,577.09 6848.24,626.53 6848.24,704.71 6884.22,740.69 v1(6916.98,740.69) 6917.48,740.19 6934.65,740.19 D4.2@6935,739.84
CAN0_N: J3.3 R2.1 U1.12 | length 461.4
  Top Layer w4: U1.12@4340.64,379.98 4358.8,379.98 4361.14,377.64 4361.14,313.44 4373.28,301.3 4437.68,301.3 4450.75,288.24 4455.71,283.27 4455.71,251.11 4453.06,248.46 ; J3.3@4359.94,123.67 4359.94,160.07 4374.77,174.9 4447.96,174.9 4455.4,182.34 4455.4,246.12 4453.06,248.46 ; R2.1@4428.53,248.46 4453.06,248.46
CAN0_P: J3.1 R1.2 U1.13 | length 460.9
  Top Layer w4: U1.13@4390.64,379.98 4372.48,379.98 4370.14,377.64 4370.14,317.17 4377.01,310.3 4441.41,310.3 4464.71,287 4464.71,251.09 4467.04,248.76 ; R1.2@4491.28,248.46 4466.75,248.46 4464.4,246.12 4464.4,182.34 4471.85,174.9 4545.04,174.9 4559.87,160.07 J3.1@4559.94,123.67
CAN2_N: J5.3 R10.1 U1.9 | length 460.9
  Top Layer w4: J5.3@4021.41,123.67 4021.41,160.07 4036.25,174.9 4109.43,174.9 4116.88,182.34 4116.88,246.12 4114.53,248.46 R10.1@4090,248.46 ; 4114.24,248.76 4116.57,251.09 4116.57,287 4139.87,310.3 4204.27,310.3 4211.14,317.17 4211.14,377.64 4208.8,379.98 U1.9@4190.64,379.98
CAN2_P: J5.1 R5.2 U1.10 | length 461.4
  Top Layer w4: R5.2@4152.76,248.46 4128.22,248.46 ; J5.1@4221.34,123.67 4221.34,160.07 4206.51,174.9 4133.32,174.9 4125.88,182.34 4125.88,246.12 4128.22,248.46 ; U1.10@4240.64,379.98 4222.48,379.98 4220.14,377.64 4220.14,313.44 4208,301.3 4143.6,301.3 4130.54,288.24 4125.57,283.27 4125.57,251.11 4128.22,248.46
